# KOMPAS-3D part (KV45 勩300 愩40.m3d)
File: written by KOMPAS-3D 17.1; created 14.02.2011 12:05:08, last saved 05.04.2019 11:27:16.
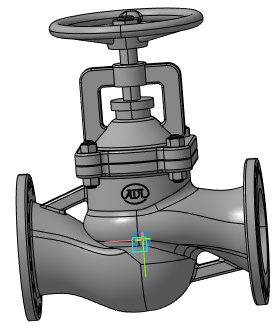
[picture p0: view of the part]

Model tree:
1. Плоскость XY
2. Плоскость ZX
3. Плоскость ZY
4. Ось X
5. Ось Y
6. Ось Z
7. Начало координат
8. Операция без истории:2
9. Смещенная плоскость:1
     Расстояние = 160
10. Эскиз:2
11. Элемент выдавливания:2
     Расстояние 1 = 24.5996; Смещение 1 = 1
